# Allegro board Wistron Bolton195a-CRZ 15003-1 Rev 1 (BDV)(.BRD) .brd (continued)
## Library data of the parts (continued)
C57 C59 C71 C81 C89 C102-C105 C108 C111 C117-C123 C134 C142 = C402H22: tolerance: 78.18134.1FL
C82 = C603H36: tolerance: 78.47510.5BL
C88 C106 C270 C288 C302 C306 C326 C445 C6511 C6522 PC4914 = C603H36: tolerance: 78.47520.5BL
C135 = C402H22: tolerance: 78.22420.5FL
C136 C147 PC4906 PC4911 PC4915 PC5103 = C402H22: tolerance: 78.10520.5FL
C175 C186 C188 C194 C254 C255 C484 = C603H36: tolerance: 78.22523.5BL
C177 C328 = C603H36: tolerance: 78.47422.5BL
C178 C324 C421 C435 C477 C486 C488 PC4917 = C603H36: tolerance: 78.10522.5BL
C179 C180 C352 PC4 PC4407 = C402H22: tolerance: 78.10422.5FL
C181 = C805H54: tolerance: 78.47522.51L
C182 C310 C313 C322 C509 C510 C512 PC4414 PC4432 PC4901 PC4908 = C402H22: tolerance: 78.10324.2FL
C184 C230 C235 C236 C266 = C1206H71: tolerance: 78.10525.22L
C185 C190 C192 C195 C197 C200 C205 C413 C420 C436 C450 PC5009 PC5015 = C805H54: tolerance: 78.10623.51L
C211 C223 PC4426-PC4428 PC4445 PC4803 PC4902 PC4903 PC4907 PC4922 PC4923 PC5006 PC5007 = C1206H71: tolerance: 78.10622.52L
C246 = C603H36: tolerance: 78.33135.1BL
C267 = C402H22: tolerance: 78.22224.2FL
C281 C323 PC4405 = C402H22: tolerance: 78.10234.1FL
C292 = C1206H71: tolerance: 78.1022S.22L
C307 C312 C375 C431 C3619 PC2 PC7 PC4415 PC4425 PC4431 PC4804 PC4805 PC4905 PC4909 PC5005 PC5008 PC5208 = C603H36: tolerance: 78.10424.2BL
C327 = C402H22: tolerance: 78.47491.4FL
C353 C354 C356-C365 C368-C371 C373 C374 C376 C377 EC302 EC326-EC330 EC708 EC709 = C402H22: tolerance: 78.5R074.1FL
C379 C388 C392-C397 = C402H22: tolerance: 78.1R574.1FL
C384 = C402H22: tolerance: 78.47134.1FL
C409-C411 C414 C422-C425 = C402H22: tolerance: 78.10324.2FL; signal model: C402H22_SCD01U50V2KX-1GP
C426 = C805H54: tolerance: 78.10620.51L
C428-C430 = C402H22: tolerance: 78.4R774.1FL
C446 = C805H54: tolerance: 78.10693.41L
C452 C460 C680 = C402H22: tolerance: 78.10034.1FL
C495 C496 = C402H22: tolerance: 78.10413.5FL; signal model: C402H22_SCD1U10V2MX-3GP
C506 C3608 C3609 C3614 C3615 C6510 C6514-C6519 C6524 C6526 C6530 C6531 PC4808 PC5012 PC5105 PC5106 PC5205-PC5207 PC5210-PC5226 PC5229 = C603H40: tolerance: 78.22610.5BL
C511 = C402-TO0D2H26: tolerance: 78.47510.5FL
C3603 C3604 C6528 C6529 = C402H22: tolerance: 78.10224.L1L
C4801 PC5110 PC5203 = C402H22: tolerance: 78.10423.2FLDL
C5001 C5002 = C603H36: tolerance: 78.10521.5BLDL
C6101 C6103 C6104 = C402H22: tolerance: 78.10422.2FL
CAM1 = 4260-F08N-00R: tolerance: 20.F2191.008
CMOS1 = SKRBAAE010: tolerance: 62.40089.071
CNVBD2 = 50228-01271-001: tolerance: 20.F1637.012
CPU1 = BGA769M24D5H76: tolerance: 71.KABIN.00U
CRS1 = PSDAT0-09GLBS1ZZ4H1-1: tolerance: 62.10051.661
D1-D3 = SOT23-2D4-312H48: tolerance: 75.00054.R7D
D4 = SOT23-2D4-312H48: tolerance: 75.00054.E7D
D5 = D4724AKH44: tolerance: 83.3R010.C8M
D7 = SOD-523-4H28: tolerance: 75.YSE05.077
D9 D12 D21 = SOT23-2D4-312H46: tolerance: 75.05125.07D
D14 = SOD323AKH40: tolerance: 83.00355.F1F
D19 = SLP2510P8-1H22: tolerance: 83.03010.0A0
D20 D24 = SOT-6H58: tolerance: 075.00005.0B7C
D29 = D5436AKH97: tolerance: 83.P6SBM.AAG
DBGH1 = A2006WV0-2DX7PSA-6T-P: tolerance: 021.D0050.0207
DCIN1 = 2DC-G726-Q15: tolerance: 22.10037.K01
DIMM1 = 1932207-1-U2: tolerance: 62.10017.N91
EC1-EC8 = C402H22: tolerance: 78.6R074.1FL
EC701 EC704 = C402H22: tolerance: 78.10034.L0L
F1 = POLYSW-4633-1H63: tolerance: 69.50013.001
F3 F6 F8 F9 = POLYSW-2114H30: tolerance: 69.48001.081
F4 F7 = POLYSW-3217-UH63: tolerance: 69.42001.291
FANC1 = 87212-0312L: tolerance: 20.F1493.003
FC1 FC4 = C402H22: tolerance: 78.33034.1FL
FC2 = C402H20: tolerance: 78.56034.1FL
G1 G2 PG4401-PG4404 = CON2C-U: tolerance: ZZ.CON2C.XXX
G3 = CON2O-U: tolerance: ZZ.CON2O.XXX
GDT1 = TVS5436-1121H105: tolerance: 069.A0007.0001
H1-H5 = GENS315R158-8-F-A: tolerance: ZZ.SCREW.541
HDD1 = C166KK-12209-L: tolerance: 022.10019.0021
HDMI1 = SKT-HDMI23-150122-9: tolerance: 62.10078.641
HDT1 = DM-ASP-137098-05-01: tolerance: ZZ.F1722.02001
HS1 HS2 = STF237R128H34: tolerance: 34.4YP25.001
HS3 = STF256R109H124: tolerance: 334.0350J.0001
HS4 HS5 = STFT256B126R113H62: tolerance: 334.01Z0E.0001
L1 = L805H42: tolerance: 68.00216.291
L3 L5 L50 L54-L56 L74 L75 = L603H38: tolerance: 68.00335.091
L4 L19 L20 = L1608-UH38: tolerance: 68.00217.351
L7 L9 L11 L13 = L1608-UH38: tolerance: 68.00206.261
L18 PR5201 PR5204 R110-R113 R121 R589 R6103 R6556 R6572 = 0R0603-PAD-1-U: tolerance: ZZ.00PAD.M21
L21 = L3330-1230H95: tolerance: 68.4R710.20S
L22-L25 L41 L44 L47 L72 = L125100-4P-4H24: tolerance: 68.00396.001; signal model: L125100-4P-4H24_COIL-90OHM-100MHZ-5-GP
L27 = L120120-5022-2H237: tolerance: 68.2201C.10Q
L38 = L603H38: tolerance: 68.00335.181
L40 = L125100-4P-4H24: tolerance: 68.00396.001
L49 = L125100-4P-4H24: tolerance: 68.00396.001; signal model: Graser_L49
L51 L53 = L603H38: tolerance: 68.00335.101
L52 = L3030-3009H40: tolerance: 68.4R710.20T
L2901 = L125100-4P-1H37: tolerance: 68.01012.201
LAN1 = QFN32J4-G2D85H36: tolerance: 71.08111.U03
LVDS19 = 196108-30041-U: tolerance: 20.K0386.030
NGFFE1 = AS0BC21-S40BE-7H: tolerance: 062.10003.0611
ODD1 = WATA-07APLDJ6U: tolerance: 020.80475.0007
ODDPW1 = CI0102M1HR0-LF: tolerance: 020.D0007.0102
PC3 PC8 = C805H58: tolerance: 78.10594.41L
PC4402 = C402H22: tolerance: 78.33134.1FLDL
PC4403 PC4442 = C402H22: tolerance: 78.68124.2FL
PC4404 PC4435 = C402H22: tolerance: 78.47034.1FL
PC4406 = C402H22: tolerance: 78.10321.2FLLL
PC4408 PC4409 PC4443 = C805H56: tolerance: 78.10622.51L
PC4410 = C402H22: tolerance: 78.56321.2FL
PC4411 = C402H22: tolerance: 78.10423.5FLLL
PC4413 = C402H22: tolerance: 78.33134.1FL
PC4416 = C402H22: tolerance: 78.47124.2FL
PC4430 = C402H22: tolerance: 078.22423.05FD
PC4437 PC4438 = C402H22: tolerance: 78.47124.2FLLL
PC4439 = C402H22: tolerance: 78.22423.5FL
PC4440 = C402H22: tolerance: 78.10423.5FLDL
PC4441 = C402H22: tolerance: 78.33124.2FL
PC4801 PC5002 PC5104 = C402H22: tolerance: 78.10224.2FLDL
PC4810 PC4919 PC4920 PC5013 = C402H22: tolerance: 78.18034.1FLDL
PC4916 PC4918 = C402H22: tolerance: 78.22034.1FLDL
PC5014 = C805H50: tolerance: 78.10623.51LDL
PC5016 = C603: tolerance: 78.33322.2BL
PC5107 = C603H40: tolerance: 78.22610.5BLDL
PC5109 = C402H22: tolerance: 78.68124.2FLDL
PG4801 PG4802 PG4901-PG4905 = GAP-CLOSE-PWR-3: tolerance: ZZ.CLOSE.001
PL4901 PL4902 = L686647-127318H119: tolerance: 68.3R31A.10V
PL4904 = L115100-2H158: tolerance: 68.R3610.10M
PL4905 = L686647-127318H119: tolerance: 68.R3310.10D
PL4906 PL5001 PL5101 = L686647-127318H119: tolerance: 68.1R51A.10F
PQ4401 PQ4403 = PPAK-8P-5262H40: tolerance: 84.06520.037
PQ4402 PQ4404 PQ4405 = PPAK-8P-5262H40: tolerance: 084.06510.0037
PQ4801 PQ4901 PQ4902 PQ5001 = PPAK-8P-3232H36: tolerance: 84.07410.A37
PQ4802 PQ4903 PQ4904 PQ5002 = PPAK-8P-3232H36: tolerance: 84.07506.037
PR1 = R2512H32: tolerance: 64.R0105.97L
PR2 PR7 R355 R356 = R402H16: tolerance: 64.30035.6DL
PR3 PR4 = R402H16: tolerance: 64.30025.6DL
PR10 PR11 PR13 PR4918 R288 R810 = R402H16: tolerance: 64.15025.6DL
PR12 PR16 PR5206 R296 R338 = R402H16: tolerance: 64.10035.6DL
PR14 PR15 R367 R537 R583 R6577 = R402H16: tolerance: 63.20334.1DL
PR17 = R402H16: tolerance: 64.20035.6DL
PR18 PR4901 R12 R86 R87 R318 R378 R382 R438 R490 R530 R559 R586 = R402H16: tolerance: 63.10434.1DL
PR161 PR4463 PR4464 PR4801 PR4929 R65 R69 R70 R73 R74 R76-R81 R83 R85 R92-R95 R122 R125-R129 R177 R285 R287 R299 R302 R303 R309 R386 R395 R396 R401 R441 R466 R474-R477 R492 R493 R497 R498 R501 R504 R505 R509-R513 R516-R518 R520 R523 R524 R533 R535 R542 R556 R561-R563 R568 R572 R616 R620 R624 R671 R698 R822-R824 R1019 R1020 R6533-R6535 R6543 R6545 R6546 R6548 R6557-R6561 R6563 R6564 R6566 R6578 = R402H16: tolerance: 63.10334.1DL
PR4202 PR4443 PR4921 PR4923 PR4925 PR5006 PR5208 PR5209 R341 R353 R354 R500 R503 R507 R514 R521 R531 R832 R1028-R1030 R6105 R6532 = R402H16: tolerance: 64.10025.6DL
PR4401 PR4435 = R402H16: tolerance: 64.27425.6DL
PR4402 PR4409 PR4424 PR4441 PR4458 PR4462 PR4814 PR5210 R339 = R402H14: tolerance: 64.10R05.6DL
PR4403 PR4428-PR4431 PR4437 PR4440 PR4444 PR4452 PR4454 PR4928 PR5018 R6 R34-R38 R53-R56 R67 R104-R106 R136 R145 R146 R152 R164-R168 R259 R261 R264 R307 R314 R440 R480 R481 R483 R486-R489 R522 R526 R534 R536 R538 R540 R541 R545 R547 R574 R575 R577 R580 R585 R602 R603 R867 R1012 R1014 R4801 R5201 R6104 R6541 = 0R0402-PAD-1: tolerance: ZZ.00PAD.M11
PR4404 = R402H16: tolerance: 64.20515.6DL
PR4405 PR4406 PR4432 PR4433 PR4802 PR4808 PR4810 PR4811 PR4902-PR4904 PR4906 PR4907 PR4910 PR4913-PR4916 PR4930 PR5002 PR5011 PR5013 PR5015-PR5017 PR5021 PR5213 = 0R0805-PAD: tolerance: ZZ.R0805.ZZZ
PR4407 PR4446 PR4450 R18 R387-R394 = R402H16: tolerance: 64.49905.6DL
PR4408 = R402H16: tolerance: 64.56215.6DLDL
PR4410 PR4453 = R402H16: tolerance: 64.26115.6DL
PR4411 = R402H16: tolerance: 64.26735.6DL
PR4412 = R402H16: tolerance: 64.16015.6DL
PR4413 = R402H16: tolerance: 64.82505.6DL
PR4414 PR4451 = R402H16: tolerance: 64.11025.6DL
PR4415 PR4417 PR4420 PR4442 PR4445 PR4455 PR4804 PR4806 PR4812 PR4905 PR4908 PR4909 PR4911 PR4912 PR4919 PR4920 PR5007 PR5009 PR5019 PR5104 = R805H24: tolerance: 63.2R231.16L
PR4416 PR4448 = NTC-402H24-U: tolerance: 69.60013.131
PR4418 = R402H16: tolerance: 64.12015.6DL
PR4421 PR4438 = R402H16: tolerance: 64.38315.6DL
PR4422 PR4439 = NTC-402H22-U: tolerance: 69.60037.021
PR4423 PR4461 = R402H16: tolerance: 64.36515.6DL
PR4425 PR4434 PR4926 = R402H16: tolerance: 64.13335.6DL
PR4426 PR4427 R350 = R805H24: tolerance: 63.1R031.16L
PR4447 R1022-R1027 = R402H14: tolerance: 63.10034.1DL
PR4449 PR4460 R1 R3 R20 R24 R60 R61 R71 R75 R130 R179 R270 R432 R478 R479 R576 R593-R596 R808 R866 R1013 R1015 R4802-R4804 R5002 R5101 R5202 R6110 R6513 R6515 R6531 R6540 R6562 R6565 R6568 R6569 = R402H16: tolerance: 63.R0034.1DL
PR4456 = R402H16: tolerance: 64.34025.6DL
PR4457 = R402H16: tolerance: 64.21515.6DL
PR4459 R5 R7 R9 R16 R17 R97-R100 R139-R142 R345 = R402H16: tolerance: 64.10015.6DL
PR4805 = R402H16: tolerance: 64.78725.6DL
PR4809 = R402H16: tolerance: 64.47035.6DL
PR4813 R96 = R402H16: tolerance: 64.11825.6DL
PR4815 R313 = R402H16: tolerance: 64.33025.6DL
PR4917 = R402H16: tolerance: 64.66515.6DL
PR4922 = R402H16: tolerance: 64.21525.6DL
PR4924 = R402H16: tolerance: 64.68025.6DL
PR4927 = R402H16: tolerance: 64.88725.6DL
PR5001 PR5103 = R402H16: tolerance: 64.5R105.6DL
PR5004 = R402H16: tolerance: 64.51015.6DL
PR5005 = 0R0603-PAD: tolerance: ZZ.R0603.ZZZ
PR5008 = R402H16: tolerance: 64.62035.6DL
PR5020 R172 = R402H16: tolerance: 64.39225.6DL
PR5022 = R402H16: tolerance: 64.R0005.6DL
PR5101 PR5102 PR5211 PR5212 R109 R115-R117 R119 R278 R346 R429 R1021 R6536-R6539 = 0R0805-PAD-1-U: tolerance: ZZ.00PAD.M31
PR5105 = R402H16: tolerance: 64.10235.6DL
PR5107 = R402H16: tolerance: 64.51025.6DL
PR5108 = R402H16: tolerance: 64.18025.6DL
PT4402 PT4403 PT4406 PT4407 PT4411 = SE361416H237: tolerance: 79.5671V.30L
PT4404 PT5001 = CT7343H83: tolerance: 79.3371V.2PL
PT4902 PT4903 = SE331721H237: tolerance: 79.22710.E0L
PU1 = SOT23-2D8-312H58: tolerance: 74.02138.03B
PU2 = SOIC8H69: tolerance: 84.04407.G37
PU4401 = QFN40-G3D5H32: tolerance: 74.62771.033
PU4801 = DFN10G3-G265175H32: tolerance: 74.08237.B73
PU4901 = QFN20-G1D75H32: tolerance: 74.08243.073
PU5001 = QFN20-G1D75H32: tolerance: 74.08207.C73
PU5101 = DFN10G3-G265175H32: tolerance: 74.08068.A43
PU5201 = SOT-23-5H52: tolerance: 74.01339.B3F
PWRBT1 = 88511-0641: tolerance: 20.K0473.006
Q1 Q39 Q4803 = SOT23DGS2D4H44: tolerance: 84.27002.W31
Q2 = SOT23CBE2D4H44: tolerance: 84.T3904.H11
Q4 Q27 Q29 Q34 Q42 Q45 Q49 Q76 = SOT-363H44: tolerance: 84.2N702.A3F
Q26 Q35 Q36 Q38 Q98 Q99 Q4808 = SOT23DGS2D4H44: tolerance: 84.2N702.J31
Q28 Q32 Q41 Q52 = SOT-23-10H44: tolerance: 84.03906.F11
Q33 Q75 Q82 Q83 Q100 Q101 Q4401 Q4807 = SOT23DGS2D4H48: tolerance: 84.2N702.E31
Q37 Q4402 = SOT23CBE2D4H44: tolerance: 84.T3904.C11
Q40 U16 U17 = SOT23DGS2D8H50: tolerance: 84.03418.A31
Q43 = SOT23DGS2D8H50: tolerance: 84.03413.B31
Q44 = SOT-23-10H44: tolerance: 84.03904.L06
Q48 Q50 Q51 Q57 Q4802 Q4804-Q4806 = SOT23DGS2D4H44: tolerance: 84.27002.Z31
Q78 = SOIC8H75: tolerance: 084.PA010.0037
Q4801 = SOT23DGS2D4H35: tolerance: 84.3K329.031
R2 R21 R23 R25-R27 R30-R33 R39-R44 R46-R48 R88-R90 R124 R175 R176 R234 R286 R306 R317 R364 R365 R379 R402 R437 R491 R546 R548-R553 R557 R560 R579 R581 R582 R584 R830 R982 R6547 R6549 R6552-R6555 R6570 R6571 R6573 R6574 R6576 = R402H16: tolerance: 63.10234.1DL
R4 = R402H16: tolerance: 64.39R25.6DL
R8 = R402H16: tolerance: 64.16915.6DL
R10 R13-R15 R807 R826-R828 = R402H16: tolerance: 64.15005.6DL
R11 = R402H16: tolerance: 64.20015.6DL
R19 R22 R49-R51 R266 R464 R813 = R402H16: tolerance: 63.30134.1DL
R28 R29 R377 = R402H16: tolerance: 64.51105.6DL
R45 R310 R319 R359 R360 R381 R383 R439 R527 R591 R592 R597-R601 R604-R609 R617 R622 R812 R4401-R4403 R6516 R6550 R6551 = R402H16: tolerance: 63.47234.1DL
R52 R131 R134 R135 R232 R515 R619 R6512 = R402H16: tolerance: 63.22234.1DL
R57 R58 = R402H16: tolerance: 63.18234.1DL
R59 = R402H16: tolerance: 63.22134.1DL
R62 R316 R376 R434 R435 R555 R578 = R402H16: tolerance: 63.47334.1DL
R63 R64 R174 R430 R431 R433 R539 R543 = R402H16: tolerance: 63.33034.1DL
R84 = R603H22: tolerance: 63.20634.15L
R101-R103 = R402H16: tolerance: 63.22034.1DL
R108 = R603H22: tolerance: 64.10045.55L
R123 R6544 = R402H16: tolerance: 63.20134.1DL
R132 R133 R6575 = R402H16: tolerance: 63.20234.1DL
R169 R809 = R402H16: tolerance: 64.20025.6DL
R235 R236 R6511 = R402H16: tolerance: 63.22334.1DL
R238 R240 R623 = R402H16: tolerance: 63.75034.1DL
R268 = R402H16: tolerance: 64.24915.6DL
R269 R802-R804 = R805H24: tolerance: 63.R0031.16L
R271 R272 = 0R0402-PAD-1: tolerance: ZZ.00PAD.M11; signal model: 0R0402-PAD-1_0R0402-PAD-2-GP
R284 = R603H22: tolerance: 63.75033.15L
R315 R380 R436 = R402H16: tolerance: 63.33434.1DL
R322 R544 = R402H14: tolerance: 64.10005.6DL
R342 = 0R1206-PAD-1: tolerance: ZZ.R1206.ZZ1
R347 = R805H24: tolerance: 63.20131.16L
R348 R349 = R1206H26: tolerance: 64.R3305.41L
R374 R375 = R402H14: tolerance: 63.10134.1DL
R384 = R402H16: tolerance: 63.10534.1DL
R463 R588 R590 = R603H22: tolerance: 63.00000.00L
R499 R508 = R402H16: tolerance: 64.17825.6DL
R502 = R402H16: tolerance: 64.64915.6DL
R519 = R402H16: tolerance: 64.95325.6DL
R529 = R402H16: tolerance: 64.47015.6DL
R587 = R402H16: tolerance: 64.12025.6DL
R610 R611 R613-R615 = R402H16: tolerance: 63.10434.L0L
R618 = R805H24: tolerance: 63.30131.16L
R621 = R805H24: tolerance: 63.15131.16L
R1031 = R603H22: tolerance: 63.33133.15L
R6517 = R402H16: tolerance: 64.82015.6DL
R6579 = R402H16: tolerance: 64.56015.6DL
RJ1 = C100LS-10809-L: tolerance: 022.10001.0041
RN1 = SMD-ARES4-2H18-U: tolerance: 66.1033A.04L
RN2 = ARES8-CN24-UH20: tolerance: 66.33036.A8L
RN3 RN5 RN12 RN15-RN17 = ARES2H16: tolerance: 66.22236.04L
RN4 RN6 RN7 RN9 RN11 RN22 = ARES8-CN24-MUH20: tolerance: 66.10336.08L
RN8 = SMD-ARES4H18: tolerance: 66.33036.04L
RN10 RN18-RN21 = ARES2H18: tolerance: 66.10336.04L
RT1 RT2 = NTC-402H22-U: tolerance: 69.60011.121
SPI1 = G6179-1000000-U: tolerance: 62.10076.011
SPK1 = 87212-04G2: tolerance: 20.F1889.004
TOUCH1 = 50228-0057C-001: tolerance: 20.F2220.005
TP1-TP18 TP23 TP24 TP27 TP29 TP30 TP33-TP35 TP64-TP70 = TPAD24: tolerance: ZZ.PAD24.001
TP19-TP22 TP25 TP28 TP31 TP32 TP55 = TPAD28-1-U: tolerance: ZZ.00PAD.1F1
TR3 = L125100-4P-1H28: tolerance: 68.10129.201; signal model: Graser_TR3
TR4 = L125100-4P-1H28: tolerance: 68.10129.201; signal model: Graser_TR4
TR5 = L125100-4P-1H28: tolerance: 68.10129.201; signal model: Graser_TR5
TR6 = L125100-4P-1H28: tolerance: 68.10129.201; signal model: Graser_TR6
TR11 TR12 TR25 TR26 = L125100-4P-1H24: tolerance: 68.11500.201; signal model: L125100-4P-1H24_COIL-50OHM-GP
TR27 TR28 = L125100-4P-1H24: tolerance: 68.11500.201
U9 U10 = SOT-6H58: tolerance: 75.09904.07C
U12 U13 = SON14J3020-G2610H32: tolerance: 74.03523.A73
U18 U20 U22 = SOT-6-1H50: tolerance: 84.06402.B3D
U23-U25 = DFN10G2510H26: tolerance: 75.01045.073
U30 = SOIC8-1H86: tolerance: 72.25640.D01
U31 = PQFP128H134: tolerance: 71.08732.00E
U38 = QFN48J6-G4D55H40: tolerance: 71.02136.B03
U39 = SOT-23-1H44: tolerance: 75.00099.07D
U48 = SOIC8H69: tolerance: 74.00358.K11
U51 = SOT-23-5H58: tolerance: 074.00524.0B9F
U56 = SOIC8H69: tolerance: 072.25010.0A01
U58 = SOIC8H69: tolerance: 72.24C64.E01
U59 = QFN20-G2D1H34: tolerance: 74.00554.073
U6502 = SOIC8H69: tolerance: 74.05606.A71
U6503 = LQFP64H63: tolerance: 71.08772.B0G
USB2S1 USB2S2 = SKT-USB6-145137-6: tolerance: 22.10218.H01
USB3S1 = SKT-USB11-139165-9: tolerance: 22.10341.B51
X1 = SMD49-6914-0403H56: tolerance: 82.30001.661
X2 = OSC-3225-4P-3H36: tolerance: 82.30026.271
X3 = OSC-3225-4P-4H36: tolerance: 82.30020.G71
XF1 = XFORM24Z151100H160: tolerance: 68.89240.30B; signal model: XFORM24Z151100H160_XFORM-24P-27-GP

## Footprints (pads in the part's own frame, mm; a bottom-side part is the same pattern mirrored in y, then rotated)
0R0402-PAD-1
  custom 0.14x0.14 smd: 1(0,0.445) 2(0,-0.445)
0R0603-PAD
  custom 0.216x0.216 smd: 1(0,0.851) 2(0,-0.673)
0R0603-PAD-1-U
  custom 0.216x0.216 smd: 1(0,0.762) 2(0,-0.762)
0R0805-PAD
  rect 1.397x1.562 smd: 1(0,0.965)
  rect 1.397x1.569 smd: 2(0,-0.965)
0R0805-PAD-1-U
  rect 1.397x1.562 smd: 1(0,0.965)
  rect 1.397x1.569 smd: 2(0,-0.965)
0R1206-PAD-1
  rect 1.651x2.057 smd: 1(0,1.397) 2(0,-1.397)
2DC-G726-Q15
  round 0.254 hole 2.413 unplated: (0,0)
  oval 2.718x1.727 hole 2.007x1.016: 1(0,7.25)
  oval 1.727x2.718 hole 1.016x2.007: 2(-3.1,6.3) 3(-5.2,6.3) 4(3.4,6.3)
  oval 1.727x3.023 hole 1.016x2.311: 5(3.75,-1) 6(-6.15,-1)
4260-F08N-00R
  rect 0.508x0.991 smd: 1(2.8,1.945) 2(2,1.945) 3(1.2,1.945) 4(0.4,1.945) 5(-0.4,1.945) 6(-1.2,1.945) 7(-2,1.945) 8(-2.8,1.945)
  rect 1.194x1.702 smd: 9(4.097,0) 10(-4.097,0)
50228-0057C-001
  rect 0.61x1.549 smd: 1(2,-2.525) 2(1,-2.525) 3(0,-2.525) 4(-1,-2.525) 5(-2,-2.525)
  rect 1.194x1.803 smd: 6(3.3,0) 7(-3.3,0)
50228-01271-001
  rect 0.61x1.549 smd: 1(5.5,-2.525) 2(4.5,-2.525) 3(3.5,-2.525) 4(2.5,-2.525) 5(1.5,-2.525) 6(0.5,-2.525) 7(-0.5,-2.525) 8(-1.5,-2.525) 9(-2.5,-2.525) 10(-3.5,-2.525) 11(-4.5,-2.525) 12(-5.5,-2.525)
  rect 1.194x1.803 smd: 13(6.8,0) 14(-6.8,0)
87212-04G2
  rect 0.406x1.651 smd: 1(-1.5,-2.577) 2(-0.5,-2.577) 3(0.5,-2.577) 4(1.5,-2.577)
  rect 1.194x1.803 smd: 5(-2.797,0) 6(2.797,0)
87212-0312L
  rect 0.61x1.549 smd: 1(-1,-2.525) 2(0,-2.525) 3(1,-2.525)
  rect 1.194x1.803 smd: 4(-2.3,0) 5(2.3,0)
88511-0641
  rect 0.305x1.295 smd: 1(-1.25,2.798) 2(-0.75,2.798) 3(-0.25,2.798) 4(0.25,2.798) 5(0.75,2.798) 6(1.25,2.798)
  rect 1.803x1.397 smd: 7(-2.902,0) 8(2.902,0)
196108-30041-U
  rect 0.508x1.295 smd: 1(-14.5,2.65) 2(-13.5,2.65) 3(-12.5,2.65) 4(-11.5,2.65) 5(-10.5,2.65) 6(-9.5,2.65) 7(-8.5,2.65) 8(-7.5,2.65) 9(-6.5,2.65) 10(-5.5,2.65) 11(-4.5,2.65) 12(-3.5,2.65) 13(-2.5,2.65) 14(-1.5,2.65) 15(-0.5,2.65) 16(0.5,2.65) 17(1.5,2.65) 18(2.5,2.65) 19(3.5,2.65) 20(4.5,2.65) 21(5.5,2.65) 22(6.5,2.65) 23(7.5,2.65) 24(8.5,2.65) 25(9.5,2.65) 26(10.5,2.65) 27(11.5,2.65) 28(12.5,2.65) 29(13.5,2.65) 30(14.5,2.65)
  rect 1.803x1.397 smd: 31(-16.65,0) 32(16.65,0)
1932207-1-U2
  round 0.254 hole 1.651 unplated: (-33.4,0)
  round 0.254 hole 1.118 unplated: (33.4,0)
  custom 0.114x0.114 smd: 1(-31.65,-4.1) 2(-31.35,4.1) 3(-31.05,-4.1) 4(-30.75,4.1) 5(-30.45,-4.1) 6(-30.15,4.1) 7(-29.85,-4.1) 8(-29.55,4.1) 9(-29.25,-4.1) 10(-28.95,4.1) 11(-28.65,-4.1) 12(-28.35,4.1) 13(-28.05,-4.1) 14(-27.75,4.1) 15(-27.45,-4.1) 16(-27.15,4.1) 17(-26.85,-4.1) 18(-26.55,4.1) 19(-26.25,-4.1) 20(-25.95,4.1) 21(-25.65,-4.1) 22(-25.35,4.1) 23(-25.05,-4.1) 24(-24.75,4.1) 25(-24.45,-4.1) 26(-24.15,4.1) 27(-23.85,-4.1) 28(-23.55,4.1) 29(-23.25,-4.1) 30(-22.95,4.1) 31(-22.65,-4.1) 32(-22.35,4.1) 33(-22.05,-4.1) 34(-21.75,4.1) 35(-21.45,-4.1) 36(-21.15,4.1) 37(-20.85,-4.1) 38(-20.55,4.1) 39(-20.25,-4.1) 40(-19.95,4.1) 41(-19.65,-4.1) 42(-19.35,4.1) 43(-19.05,-4.1) 44(-18.75,4.1) 45(-18.45,-4.1) 46(-18.15,4.1) 47(-17.85,-4.1) 48(-17.55,4.1) 49(-17.25,-4.1) 50(-16.95,4.1) 51(-16.65,-4.1) 52(-16.35,4.1) 53(-16.05,-4.1) 54(-15.75,4.1) 55(-15.45,-4.1) 56(-15.15,4.1) 57(-14.85,-4.1) 58(-14.55,4.1) 59(-14.25,-4.1) 60(-13.95,4.1) 61(-13.65,-4.1) 62(-13.35,4.1) 63(-13.05,-4.1) 64(-12.75,4.1) 65(-12.45,-4.1) 66(-12.15,4.1) 67(-11.85,-4.1) 68(-11.55,4.1) 69(-11.25,-4.1) 70(-10.95,4.1) 71(-10.65,-4.1) 72(-10.35,4.1) 73(-7.65,-4.1) 74(-7.35,4.1) 75(-7.05,-4.1) 76(-6.75,4.1) 77(-6.45,-4.1) 78(-6.15,4.1) 79(-5.85,-4.1) 80(-5.55,4.1) 81(-5.25,-4.1) 82(-4.95,4.1) 83(-4.65,-4.1) 84(-4.35,4.1) 85(-4.05,-4.1) 86(-3.75,4.1) 87(-3.45,-4.1) 88(-3.15,4.1) 89(-2.85,-4.1) 90(-2.55,4.1) 91(-2.25,-4.1) 92(-1.95,4.1) 93(-1.65,-4.1) 94(-1.35,4.1) 95(-1.05,-4.1) 96(-0.75,4.1) 97(-0.45,-4.1) 98(-0.15,4.1) 99(0.15,-4.1) 100(0.45,4.1) 101(0.75,-4.1) 102(1.05,4.1) 103(1.35,-4.1) 104(1.65,4.1) 105(1.95,-4.1) 106(2.25,4.1) 107(2.55,-4.1) 108(2.85,4.1) 109(3.15,-4.1) 110(3.45,4.1) 111(3.75,-4.1) 112(4.05,4.1) 113(4.35,-4.1) 114(4.65,4.1) 115(4.95,-4.1) 116(5.25,4.1) 117(5.55,-4.1) 118(5.85,4.1) 119(6.15,-4.1) 120(6.45,4.1) 121(6.75,-4.1) 122(7.05,4.1) 123(7.35,-4.1) 124(7.65,4.1) 125(7.95,-4.1) 126(8.25,4.1) 127(8.55,-4.1) 128(8.85,4.1) 129(9.15,-4.1) 130(9.45,4.1) 131(9.75,-4.1) 132(10.05,4.1) 133(10.35,-4.1) 134(10.65,4.1) 135(10.95,-4.1) 136(11.25,4.1) 137(11.55,-4.1) 138(11.85,4.1) 139(12.15,-4.1) 140(12.45,4.1) 141(12.75,-4.1) 142(13.05,4.1) 143(13.35,-4.1) 144(13.65,4.1) 145(13.95,-4.1) 146(14.25,4.1) 147(14.55,-4.1) 148(14.85,4.1) 149(15.15,-4.1) 150(15.45,4.1) 151(15.75,-4.1) 152(16.05,4.1) 153(16.35,-4.1) 154(16.65,4.1) 155(16.95,-4.1) 156(17.25,4.1) 157(17.55,-4.1) 158(17.85,4.1) 159(18.15,-4.1) 160(18.45,4.1) 161(18.75,-4.1) 162(19.05,4.1) 163(19.35,-4.1) 164(19.65,4.1) 165(19.95,-4.1) 166(20.25,4.1) 167(20.55,-4.1) 168(20.85,4.1) 169(21.15,-4.1) 170(21.45,4.1) 171(21.75,-4.1) 172(22.05,4.1) 173(22.35,-4.1) 174(22.65,4.1) 175(22.95,-4.1) 176(23.25,4.1) 177(23.55,-4.1) 178(23.85,4.1) 179(24.15,-4.1) 180(24.45,4.1) 181(24.75,-4.1) 182(25.05,4.1) 183(25.35,-4.1) 184(25.65,4.1) 185(25.95,-4.1) 186(26.25,4.1) 187(26.55,-4.1) 188(26.85,4.1) 189(27.15,-4.1) 190(27.45,4.1) 191(27.75,-4.1) 192(28.05,4.1) 193(28.35,-4.1) 194(28.65,4.1) 195(28.95,-4.1) 196(29.25,4.1) 197(29.55,-4.1) 198(29.85,4.1) 199(30.15,-4.1) 200(30.45,4.1) 201(30.75,-4.1) 202(31.05,4.1) 203(31.35,-4.1) 204(31.65,4.1)
  rect 3.505x4.597 smd: 205(-32.8,12) 206(32.8,12)
A2006WV0-2DX7PSA-6T-P
  rect 0.813x2.692 smd: 1(-6,2.1) 2(-6,-2.1) 3(-4,2.1) 4(-4,-2.1) 5(-2,2.1) 7(0,2.1) 8(0,-2.1) 9(2,2.1) 10(2,-2.1) 11(4,2.1) 12(4,-2.1) 13(6,2.1) 14(6,-2.1)
  rect 0.025x0.025 smd: 6(-2,-2.1)
AAA-BAT-034-K01
  round 0.254 hole 1.067 unplated: (-7.5,0)
  round 0.254 hole 1.372 unplated: (0,0)
  rect 2.794x3.607 smd: 1(6.2,0)
  rect 2.997x2.591 smd: 2(-15.1,0)
ARES2H16
  rect 0.356x0.66 smd: 1(-0.325,-0.599) 2(0.325,-0.599) 3(0.325,0.599) 4(-0.325,0.599)
ARES2H18
  rect 0.356x0.66 smd: 1(-0.325,-0.599) 2(0.325,-0.599) 3(0.325,0.599) 4(-0.325,0.599)
ARES8-CN24-MUH20
  rect 0.61x0.66 smd: 1(-0.9,-0.486) 4(0.9,-0.486) 5(0.9,0.486) 8(-0.9,0.486)
  rect 0.305x0.66 smd: 2(-0.25,-0.486) 3(0.25,-0.486) 6(0.25,0.486) 7(-0.25,0.486)
ARES8-CN24-UH20
  rect 0.61x0.66 smd: 1(-0.9,-0.486) 4(0.9,-0.486) 5(0.9,0.486) 8(-0.9,0.486)
  rect 0.305x0.66 smd: 2(-0.25,-0.486) 3(0.25,-0.486) 6(0.25,0.486) 7(-0.25,0.486)
AS0BC21-S40BE-7H
  round 0.254 hole 1.168 unplated: (-10,0)
  round 0.254 hole 1.651 unplated: (10,0)
  rect 0.305x1.549 smd: 1(-9.25,5.275) 2(-9,-2.275) 3(-8.75,5.275) 4(-8.5,-2.275) 5(-8.25,5.275) 6(-8,-2.275) 7(-7.75,5.275) 8(-7.5,-2.275) 9(-7.25,5.275) 10(-7,-2.275) 11(-6.75,5.275) 12(-6.5,-2.275) 13(-6.25,5.275) 14(-6,-2.275) 15(-5.75,5.275) 16(-5.5,-2.275) 17(-5.25,5.275) 18(-5,-2.275) 19(-4.75,5.275) 20(-4.5,-2.275) 21(-4.25,5.275) 22(-4,-2.275) 23(-3.75,5.275) 32(-1.5,-2.275) 33(-1.25,5.275) 34(-1,-2.275) 35(-0.75,5.275) 36(-0.5,-2.275) 37(-0.25,5.275) 38(0,-2.275) 39(0.25,5.275) 40(0.5,-2.275) 41(0.75,5.275) 42(1,-2.275) 43(1.25,5.275) 44(1.5,-2.275) 45(1.75,5.275) 46(2,-2.275) 47(2.25,5.275) 48(2.5,-2.275) 49(2.75,5.275) 50(3,-2.275) 51(3.25,5.275) 52(3.5,-2.275) 53(3.75,5.275) 54(4,-2.275) 55(4.25,5.275) 56(4.5,-2.275) 57(4.75,5.275) 58(5,-2.275) 59(5.25,5.275) 60(5.5,-2.275) 61(5.75,5.275) 62(6,-2.275) 63(6.25,5.275) 64(6.5,-2.275) 65(6.75,5.275) 66(7,-2.275) 67(7.25,5.275) 68(7.5,-2.275) 69(7.75,5.275) 70(8,-2.275) 71(8.25,5.275) 72(8.5,-2.275) 73(8.75,5.275) 74(9,-2.275) 75(9.25,5.275)
  rect 1.194x2.743 smd: 76(-10.35,4.5) 77(10.35,4.5)
BGA769M24D5H76
  round 0.4 smd: A2(-10.7,11.3) A3(-9.95,11.3) A39(9.95,11.3) A40(10.7,11.3) AA4(-9.2,0) AA5(-8.4,0) AA7(-7.6,0) AA8(-6.8,0) AA10(-6,0) AA11(-5,0) AA13(-4,0) AA15(-3,0) AA17(-2,0) AA19(-1,0) AA21(0,0) AA23(1,0) AA25(2,0) AA27(3,0) AA29(4,0) AA31(5,0) AA32(6,0) AA34(6.8,0) AA35(7.6,0) AA37(8.4,0) AA38(9.2,0) AC4(-9.2,-1.1) AC5(-8.4,-1.1) AC7(-7.6,-1.1) AC8(-6.8,-1.1) AC10(-6,-1.1) AC11(-5,-1) AC13(-4,-1) AC15(-3,-1) AC17(-2,-1) AC19(-1,-1) AC21(0,-1) AC23(1,-1) AC25(2,-1) AC27(3,-1) AC29(4,-1) AC31(5,-1) AC32(6,-1.1) AC34(6.8,-1.1) AC35(7.6,-1.1) AC37(8.4,-1.1) AC38(9.2,-1.1) AE4(-9.2,-2.2) AE5(-8.4,-2.2) AE7(-7.6,-2.2) AE8(-6.8,-2.2) AE10(-6,-2.2) AE11(-5,-2) AE13(-4,-2) AE15(-3,-2) AE17(-2,-2) AE19(-1,-2) AE21(0,-2) AE23(1,-2) AE25(2,-2) AE27(3,-2) AE29(4,-2) AE31(5,-2) AE32(6,-2.2) AE34(6.8,-2.2) AE35(7.6,-2.2) AE37(8.4,-2.2) AE38(9.2,-2.2) AG4(-9.2,-3.3) AG5(-8.4,-3.3) AG7(-7.6,-3.3) AG8(-6.8,-3.3) AG10(-6,-3.3) AG11(-5,-3) AG13(-4,-3) AG15(-3,-3) AG17(-2,-3) AG19(-1,-3) AG21(0,-3) AG23(1,-3) AG25(2,-3) AG27(3,-3) AG29(4,-3) AG31(5,-3) AG32(6,-3.3) AG34(6.8,-3.3) AG35(7.6,-3.3) AG37(8.4,-3.3) AG38(9.2,-3.3) AJ4(-9.2,-4.4) AJ5(-8.4,-4.4) AJ7(-7.6,-4.4) AJ8(-6.8,-4.4) AJ10(-6,-4.4) AJ11(-5,-4) AJ13(-4,-4) AJ15(-3,-4) AJ17(-2,-4) AJ19(-1,-4) AJ21(0,-4) AJ23(1,-4) AJ25(2,-4) AJ27(3,-4) AJ29(4,-4) AJ31(5,-4) AJ32(6,-4.4) AJ34(6.8,-4.4) AJ35(7.6,-4.4) AJ37(8.4,-4.4) AJ38(9.2,-4.4) AL4(-9.2,-5.5) AL5(-8.4,-5.5) AL7(-7.6,-5.5) AL8(-6.8,-5.5) AL10(-6,-5.5) AL11(-5,-5) AL13(-4,-5) AL15(-3,-5) AL17(-2,-5) AL19(-1,-5) AL21(0,-5) AL23(1,-5) AL25(2,-5) AL27(3,-5) AL29(4,-5) AL31(5,-5) AL32(6,-5.5) AL34(6.8,-5.5) AL35(7.6,-5.5) AL37(8.4,-5.5) AL38(9.2,-5.5) AM11(-5.5,-6) AM13(-4.4,-6) AM15(-3.3,-6) AM17(-2.2,-6) AM19(-1.1,-6) AM21(0,-6) AM23(1.1,-6) AM25(2.2,-6) AM27(3.3,-6) AM29(4.4,-6) AM31(5.5,-6) AN4(-9.2,-6.6) AN5(-8.4,-6.6) AN7(-7.6,-6.6) AN8(-6.8,-6.6) AN34(6.8,-6.6) AN35(7.6,-6.6) AN37(8.4,-6.6) AN38(9.2,-6.6) AP11(-5.5,-6.8) AP13(-4.4,-6.8) AP15(-3.3,-6.8) AP17(-2.2,-6.8) AP19(-1.1,-6.8) AP21(0,-6.8) AP23(1.1,-6.8) AP25(2.2,-6.8) AP27(3.3,-6.8) AP29(4.4,-6.8) AP31(5.5,-6.8) AR4(-9.2,-7.7) AR5(-8.4,-7.7) AR7(-7.6,-7.7) AR11(-5.5,-7.6) AR13(-4.4,-7.6) AR15(-3.3,-7.6) AR17(-2.2,-7.6) AR19(-1.1,-7.6) AR21(0,-7.6) AR23(1.1,-7.6) AR25(2.2,-7.6) AR27(3.3,-7.6) AR29(4.4,-7.6) AR31(5.5,-7.6) AR35(7.6,-7.7) AR37(8.4,-7.7) AR38(9.2,-7.7) AU4(-9.2,-8.8) AU7(-7.7,-8.4) AU9(-6.6,-8.4) AU11(-5.5,-8.4) AU13(-4.4,-8.4) AU15(-3.3,-8.4) AU17(-2.2,-8.4) AU19(-1.1,-8.4) AU21(0,-8.4) AU23(1.1,-8.4) AU25(2.2,-8.4) AU27(3.3,-8.4) AU29(4.4,-8.4) AU31(5.5,-8.4) AU33(6.6,-8.4) AU35(7.7,-8.4) AU38(9.2,-8.8) AV7(-7.7,-9.2) AV9(-6.6,-9.2) AV11(-5.5,-9.2) AV13(-4.4,-9.2) AV15(-3.3,-9.2) AV17(-2.2,-9.2) AV19(-1.1,-9.2) AV21(0,-9.2) AV23(1.1,-9.2) AV25(2.2,-9.2) AV27(3.3,-9.2) AV29(4.4,-9.2) AV31(5.5,-9.2) AV33(6.6,-9.2) AV35(7.7,-9.2) AW1(-11.3,-9.95) AW41(11.3,-9.95) AY1(-11.3,-10.7) AY2(-10.6,-10.6) AY40(10.6,-10.6) AY41(11.3,-10.7) B1(-11.3,10.7) B2(-10.6,10.6) B40(10.6,10.6) B41(11.3,10.7) BA2(-10.7,-11.3) BA3(-9.95,-11.3) BA39(9.95,-11.3) BA40(10.7,-11.3) C1(-11.3,9.95) C41(11.3,9.95) D7(-7.7,9.2) D9(-6.6,9.2) D11(-5.5,9.2) D13(-4.4,9.2) D15(-3.3,9.2) D17(-2.2,9.2) D19(-1.1,9.2) D21(0,9.2) D23(1.1,9.2) D25(2.2,9.2) D27(3.3,9.2) D29(4.4,9.2) D31(5.5,9.2) D33(6.6,9.2) D35(7.7,9.2) E4(-9.2,8.8) E7(-7.7,8.4) E9(-6.6,8.4) E11(-5.5,8.4) E13(-4.4,8.4) E15(-3.3,8.4) E17(-2.2,8.4) E19(-1.1,8.4) E21(0,8.4) E23(1.1,8.4) E25(2.2,8.4) E27(3.3,8.4) E29(4.4,8.4) E31(5.5,8.4) E33(6.6,8.4) E35(7.7,8.4) E38(9.2,8.8) G4(-9.2,7.7) G5(-8.4,7.7) G7(-7.6,7.7) G11(-5.5,7.6) G13(-4.4,7.6) G15(-3.3,7.6) G17(-2.2,7.6) G19(-1.1,7.6) G21(0,7.6) G23(1.1,7.6) G25(2.2,7.6) G27(3.3,7.6) G29(4.4,7.6) G31(5.5,7.6) G35(7.6,7.7) G37(8.4,7.7) G38(9.2,7.7) H11(-5.5,6.8) H13(-4.4,6.8) H15(-3.3,6.8) H17(-2.2,6.8) H19(-1.1,6.8) H21(0,6.8) H23(1.1,6.8) H25(2.2,6.8) H27(3.3,6.8) H29(4.4,6.8) H31(5.5,6.8) J4(-9.2,6.6) J5(-8.4,6.6) J7(-7.6,6.6) J8(-6.8,6.6) J34(6.8,6.6) J35(7.6,6.6) J37(8.4,6.6) J38(9.2,6.6) K11(-5.5,6) K13(-4.4,6) K15(-3.3,6) K17(-2.2,6) K19(-1.1,6) K21(0,6) K23(1.1,6) K25(2.2,6) K27(3.3,6) K29(4.4,6) K31(5.5,6) L4(-9.2,5.5) L5(-8.4,5.5) L7(-7.6,5.5) L8(-6.8,5.5) L10(-6,5.5) L11(-5,5) L13(-4,5) L15(-3,5) L17(-2,5) L19(-1,5) L21(0,5) L23(1,5) L25(2,5) L27(3,5) L29(4,5) L31(5,5) L32(6,5.5) L34(6.8,5.5) L35(7.6,5.5) L37(8.4,5.5) L38(9.2,5.5) N4(-9.2,4.4) N5(-8.4,4.4) N7(-7.6,4.4) N8(-6.8,4.4) N10(-6,4.4) N11(-5,4) N13(-4,4) N15(-3,4) N17(-2,4) N19(-1,4) N21(0,4) N23(1,4) N25(2,4) N27(3,4) N29(4,4) N31(5,4) N32(6,4.4) N34(6.8,4.4) N35(7.6,4.4) N37(8.4,4.4) N38(9.2,4.4) R4(-9.2,3.3) R5(-8.4,3.3) R7(-7.6,3.3) R8(-6.8,3.3) R10(-6,3.3) R11(-5,3) R13(-4,3) R15(-3,3) R17(-2,3) R19(-1,3) R21(0,3) R23(1,3) R25(2,3) R27(3,3) R29(4,3) R31(5,3) R32(6,3.3) R34(6.8,3.3) R35(7.6,3.3) R37(8.4,3.3) R38(9.2,3.3) U4(-9.2,2.2) U5(-8.4,2.2) U7(-7.6,2.2) U8(-6.8,2.2) U10(-6,2.2) U11(-5,2) U13(-4,2) U15(-3,2) U17(-2,2) U19(-1,2) U21(0,2) U23(1,2) U25(2,2) U27(3,2) U29(4,2) U31(5,2) U32(6,2.2) U34(6.8,2.2) U35(7.6,2.2) U37(8.4,2.2) U38(9.2,2.2) W4(-9.2,1.1) W5(-8.4,1.1) W7(-7.6,1.1) W8(-6.8,1.1) W10(-6,1.1) W11(-5,1) W13(-4,1) W15(-3,1) W17(-2,1) W19(-1,1) W21(0,1) W23(1,1) W25(2,1) W27(3,1) W29(4,1) W31(5,1) W32(6,1.1) W34(6.8,1.1) W35(7.6,1.1) W37(8.4,1.1) W38(9.2,1.1)
  round 0.3 smd: A4(-9.35,10.95) A5(-8.8,11.3) A6(-8.25,10.95) A7(-7.7,11.3) A8(-7.15,10.95) A9(-6.6,11.3) A10(-6.05,10.95) A11(-5.5,11.3) A12(-4.95,10.95) A13(-4.4,11.3) A14(-3.85,10.95) A15(-3.3,11.3) A16(-2.75,10.95) A17(-2.2,11.3) A18(-1.65,10.95) A19(-1.1,11.3) A20(-0.55,10.95) A21(0,11.3) A22(0.55,10.95) A23(1.1,11.3) A24(1.65,10.95) A25(2.2,11.3) A26(2.75,10.95) A27(3.3,11.3) A28(3.85,10.95) A29(4.4,11.3) A30(4.95,10.95) A31(5.5,11.3) A32(6.05,10.95) A33(6.6,11.3) A34(7.15,10.95) A35(7.7,11.3) A36(8.25,10.95) A37(8.8,11.3) A38(9.35,10.95) AA1(-11.3,0) AA2(-10.6,0) AA3(-9.9,0) AA39(9.9,0) AA40(10.6,0) AA41(11.3,0) AB1(-10.95,-0.55) AB2(-10.25,-0.55) AB40(10.25,-0.55) AB41(10.95,-0.55) AC1(-11.3,-1.1) AC2(-10.6,-1.1) AC3(-9.9,-1.1) AC39(9.9,-1.1) AC40(10.6,-1.1) AC41(11.3,-1.1) AD1(-10.95,-1.65) AD2(-10.25,-1.65) AD40(10.25,-1.65) AD41(10.95,-1.65) AE1(-11.3,-2.2) AE2(-10.6,-2.2) AE3(-9.9,-2.2) AE39(9.9,-2.2) AE40(10.6,-2.2) AE41(11.3,-2.2) AF1(-10.95,-2.75) AF2(-10.25,-2.75) AF40(10.25,-2.75) AF41(10.95,-2.75) AG1(-11.3,-3.3) AG2(-10.6,-3.3) AG3(-9.9,-3.3) AG39(9.9,-3.3) AG40(10.6,-3.3) AG41(11.3,-3.3) AH1(-10.95,-3.85) AH2(-10.25,-3.85) AH40(10.25,-3.85) AH41(10.95,-3.85) AJ1(-11.3,-4.4) AJ2(-10.6,-4.4) AJ3(-9.9,-4.4) AJ39(9.9,-4.4) AJ40(10.6,-4.4) AJ41(11.3,-4.4) AK1(-10.95,-4.95) AK2(-10.25,-4.95) AK40(10.25,-4.95) AK41(10.95,-4.95) AL1(-11.3,-5.5) AL2(-10.6,-5.5) AL3(-9.9,-5.5) AL39(9.9,-5.5) AL40(10.6,-5.5) AL41(11.3,-5.5) AM1(-10.95,-6.05) AM2(-10.25,-6.05) AM40(10.25,-6.05) AM41(10.95,-6.05) AN1(-11.3,-6.6) AN2(-10.6,-6.6) AN3(-9.9,-6.6) AN39(9.9,-6.6) AN40(10.6,-6.6) AN41(11.3,-6.6) AP1(-10.95,-7.15) AP2(-10.25,-7.15) AP40(10.25,-7.15) AP41(10.95,-7.15) AR1(-11.3,-7.7) AR2(-10.6,-7.7) AR3(-9.9,-7.7) AR39(9.9,-7.7) AR40(10.6,-7.7) AR41(11.3,-7.7) AT1(-10.95,-8.25) AT2(-10.25,-8.25) AT40(10.25,-8.25) AT41(10.95,-8.25) AU1(-11.3,-8.8) AU2(-10.6,-8.8) AU3(-9.9,-8.8) AU39(9.9,-8.8) AU40(10.6,-8.8) AU41(11.3,-8.8) AV1(-10.95,-9.35) AV2(-10.25,-9.35) AV40(10.25,-9.35) AV41(10.95,-9.35) AW2(-10.6,-9.9) AW3(-9.9,-9.9) AW5(-8.8,-9.9) AW7(-7.7,-9.9) AW9(-6.6,-9.9) AW11(-5.5,-9.9) AW13(-4.4,-9.9) AW15(-3.3,-9.9) AW17(-2.2,-9.9) AW19(-1.1,-9.9) AW21(0,-9.9) AW23(1.1,-9.9) AW25(2.2,-9.9) AW27(3.3,-9.9) AW29(4.4,-9.9) AW31(5.5,-9.9) AW33(6.6,-9.9) AW35(7.7,-9.9) AW37(8.8,-9.9) AW39(9.9,-9.9) AW40(10.6,-9.9) AY3(-9.9,-10.6) AY4(-9.35,-10.25) AY5(-8.8,-10.6) AY6(-8.25,-10.25) AY7(-7.7,-10.6) AY8(-7.15,-10.25) AY9(-6.6,-10.6) AY10(-6.05,-10.25) AY11(-5.5,-10.6) AY12(-4.95,-10.25) AY13(-4.4,-10.6) AY14(-3.85,-10.25) AY15(-3.3,-10.6) AY16(-2.75,-10.25) AY17(-2.2,-10.6) AY18(-1.65,-10.25) AY19(-1.1,-10.6) AY20(-0.55,-10.25) AY21(0,-10.6) AY22(0.55,-10.25) AY23(1.1,-10.6) AY24(1.65,-10.25) AY25(2.2,-10.6) AY26(2.75,-10.25) AY27(3.3,-10.6) AY28(3.85,-10.25) AY29(4.4,-10.6) AY30(4.95,-10.25) AY31(5.5,-10.6) AY32(6.05,-10.25) AY33(6.6,-10.6) AY34(7.15,-10.25) AY35(7.7,-10.6) AY36(8.25,-10.25) AY37(8.8,-10.6) AY38(9.35,-10.25) AY39(9.9,-10.6) B3(-9.9,10.6) B4(-9.35,10.25) B5(-8.8,10.6) B6(-8.25,10.25) B7(-7.7,10.6) B8(-7.15,10.25) B9(-6.6,10.6) B10(-6.05,10.25) B11(-5.5,10.6) B12(-4.95,10.25) B13(-4.4,10.6) B14(-3.85,10.25) B15(-3.3,10.6) B16(-2.75,10.25) B17(-2.2,10.6) B18(-1.65,10.25) B19(-1.1,10.6) B20(-0.55,10.25) B21(0,10.6) B22(0.55,10.25) B23(1.1,10.6) B24(1.65,10.25) B25(2.2,10.6) B26(2.75,10.25) B27(3.3,10.6) B28(3.85,10.25) B29(4.4,10.6) B30(4.95,10.25) B31(5.5,10.6) B32(6.05,10.25) B33(6.6,10.6) B34(7.15,10.25) B35(7.7,10.6) B36(8.25,10.25) B37(8.8,10.6) B38(9.35,10.25) B39(9.9,10.6) BA4(-9.35,-10.95) BA5(-8.8,-11.3) BA6(-8.25,-10.95) BA7(-7.7,-11.3) BA8(-7.15,-10.95) BA9(-6.6,-11.3) BA10(-6.05,-10.95) BA11(-5.5,-11.3) BA12(-4.95,-10.95) BA13(-4.4,-11.3) BA14(-3.85,-10.95) BA15(-3.3,-11.3) BA16(-2.75,-10.95) BA17(-2.2,-11.3) BA18(-1.65,-10.95) BA19(-1.1,-11.3) BA20(-0.55,-10.95) BA21(0,-11.3) BA22(0.55,-10.95) BA23(1.1,-11.3) BA24(1.65,-10.95) BA25(2.2,-11.3) BA26(2.75,-10.95) BA27(3.3,-11.3) BA28(3.85,-10.95) BA29(4.4,-11.3) BA30(4.95,-10.95) BA31(5.5,-11.3) BA32(6.05,-10.95) BA33(6.6,-11.3) BA34(7.15,-10.95) BA35(7.7,-11.3) BA36(8.25,-10.95) BA37(8.8,-11.3) BA38(9.35,-10.95) C2(-10.6,9.9) C3(-9.9,9.9) C5(-8.8,9.9) C7(-7.7,9.9) C9(-6.6,9.9) C11(-5.5,9.9) C13(-4.4,9.9) C15(-3.3,9.9) C17(-2.2,9.9) C19(-1.1,9.9) C21(0,9.9) C23(1.1,9.9) C25(2.2,9.9) C27(3.3,9.9) C29(4.4,9.9) C31(5.5,9.9) C33(6.6,9.9) C35(7.7,9.9) C37(8.8,9.9) C39(9.9,9.9) C40(10.6,9.9) D1(-10.95,9.35) D2(-10.25,9.35) D40(10.25,9.35) D41(10.95,9.35) E1(-11.3,8.8) E2(-10.6,8.8) E3(-9.9,8.8) E39(9.9,8.8) E40(10.6,8.8) E41(11.3,8.8) F1(-10.95,8.25) F2(-10.25,8.25) F40(10.25,8.25) F41(10.95,8.25) G1(-11.3,7.7) G2(-10.6,7.7) G3(-9.9,7.7) G39(9.9,7.7) G40(10.6,7.7) G41(11.3,7.7) H1(-10.95,7.15) H2(-10.25,7.15) H40(10.25,7.15) H41(10.95,7.15) J1(-11.3,6.6) J2(-10.6,6.6) J3(-9.9,6.6) J39(9.9,6.6) J40(10.6,6.6) J41(11.3,6.6) K1(-10.95,6.05) K2(-10.25,6.05) K40(10.25,6.05) K41(10.95,6.05) L1(-11.3,5.5) L2(-10.6,5.5) L3(-9.9,5.5) L39(9.9,5.5) L40(10.6,5.5) L41(11.3,5.5) M1(-10.95,4.95) M2(-10.25,4.95) M40(10.25,4.95) M41(10.95,4.95) N1(-11.3,4.4) N2(-10.6,4.4) N3(-9.9,4.4) N39(9.9,4.4) N40(10.6,4.4) N41(11.3,4.4) P1(-10.95,3.85) P2(-10.25,3.85) P40(10.25,3.85) P41(10.95,3.85) R1(-11.3,3.3) R2(-10.6,3.3) R3(-9.9,3.3) R39(9.9,3.3) R40(10.6,3.3) R41(11.3,3.3) T1(-10.95,2.75) T2(-10.25,2.75) T40(10.25,2.75) T41(10.95,2.75) U1(-11.3,2.2) U2(-10.6,2.2) U3(-9.9,2.2) U39(9.9,2.2) U40(10.6,2.2) U41(11.3,2.2) V1(-10.95,1.65) V2(-10.25,1.65) V40(10.25,1.65) V41(10.95,1.65) W1(-11.3,1.1) W2(-10.6,1.1) W3(-9.9,1.1) W39(9.9,1.1) W40(10.6,1.1) W41(11.3,1.1) Y1(-10.95,0.55) Y2(-10.25,0.55) Y40(10.25,0.55) Y41(10.95,0.55)
C100LS-10809-L
  round 1.27 hole 0.914: 1(3.556,6.06) 2(2.54,4.96) 3(1.524,6.06) 4(0.508,4.96) 5(-0.508,6.06) 6(-1.524,4.96) 7(-2.54,6.06) 8(-3.556,4.96)
  oval 1.321x3.124 hole 0.61x2.413: 9(8.3,0) 10(-8.3,0)
C166KK-12209-L
  round 0.254 hole 1.27 unplated: (-15.595,0) (15.595,0)
  oval 1.727x3.124 hole 1.016x2.413: 23(18.075,1.11) 24(-18.075,1.11)
  oval 1.041x1.168 hole 0.762: P1(1.905,1.84) P2(0.635,1.84) P3(-0.635,1.84) P4(-1.905,1.84) P5(-3.175,1.84) P6(-4.445,1.84) P7(-5.715,1.84) P8(-6.985,1.84) P9(-8.255,1.84) P10(-9.525,1.84) P11(-10.795,1.84) P12(-12.065,1.84) P13(-13.335,1.84) P14(-14.605,1.84) P15(-15.875,1.84) S1(15.875,1.84) S2(14.605,1.84) S3(13.335,1.84) S4(12.065,1.84) S5(10.795,1.84) S6(9.525,1.84) S7(8.255,1.84)
C402-TO0D2H26
  custom 0.152x0.152 smd: 1(0,0.457) 2(0,-0.457)
C402H20
  custom 0.152x0.152 smd: 1(0,0.445) 2(0,-0.445)
C402H22
  custom 0.152x0.152 smd: 1(0,0.445) 2(0,-0.445)
C603
  custom 0.216x0.216 smd: 1(0,0.762) 2(0,-0.762)
C603H36
  custom 0.216x0.216 smd: 1(0,0.762) 2(0,-0.762)
C603H38
  custom 0.216x0.216 smd: 1(0,0.762) 2(0,-0.762)
C603H40
  custom 0.216x0.216 smd: 1(0,0.762) 2(0,-0.762)
C805H50
  rect 1.397x1.143 smd: 1(0,0.965) 2(0,-0.965)
C805H54
  rect 1.397x1.143 smd: 1(0,0.965) 2(0,-0.965)
C805H56
  rect 1.397x1.143 smd: 1(0,0.965) 2(0,-0.965)
C805H58
  rect 1.397x1.143 smd: 1(0,0.965) 2(0,-0.965)
C1206H71
  rect 1.651x1.27 smd: 1(0,1.397) 2(0,-1.397)
CI0102M1HR0-LF
  rect 0.991x3.505 smd: 1(1,-5.75) 2(-1,-5.75)
  rect 1.499x3.404 smd: 3(3.35,0) 4(-3.35,0)
CON2C-U
  custom 0.171x0.171 smd: 1(0,0.533) 2(0,-0.533)
CON2O-U
  custom 0.159x0.159 smd: 1(0,0.254) 2(0,-0.254)
CT7343H83
  rect 2.413x2.286 smd: 1(0,3.15) 2(0,-3.15)
D4724AKH44
  rect 2.007x1.549 smd: A(0,2.221) K(0,-2.221)
D5436AKH97
  rect 2.286x2.032 smd: A(0,2.438) K(0,-2.438)
DFN10G3-G265175H32
  rect 0.305x0.914 smd: 1(1,1.549) 2(0.5,1.549) 3(0,1.549) 4(-0.5,1.549) 5(-1,1.549) 6(-1,-1.549) 7(-0.5,-1.549) 8(0,-1.549) 9(0.5,-1.549) 10(1,-1.549)
  rect 2.642x1.753 smd: 11(0,0)
DFN10G2510H26
  rect 0.305x0.787 smd: 1(1,0.494) 5(-1,0.494) 6(-1,-0.494) 10(1,-0.494)
  rect 0.254x0.787 smd: 2(0.521,0.494) 4(-0.521,0.494) 7(-0.521,-0.494) 9(0.521,-0.494)
  rect 0.025x0.025 smd: 3(0,0.494)
  rect 0.406x1.753 smd: 8(0,-0.494)
DM-ASP-137098-05-01
  rect 0.737x2.794 smd: 1(-5.715,-2.035) 2(-5.715,2.035) 3(-4.445,-2.035) 4(-4.445,2.035) 5(-3.175,-2.035) 6(-3.175,2.035) 7(-1.905,-2.035) 8(-1.905,2.035) 9(-0.635,-2.035) 10(-0.635,2.035) 11(0.635,-2.035) 12(0.635,2.035) 13(1.905,-2.035) 14(1.905,2.035) 15(3.175,-2.035) 16(3.175,2.035) 17(4.445,-2.035) 18(4.445,2.035) 19(5.715,-2.035) 20(5.715,2.035)
G6179-1000000-U
  rect 0.635x2.108 smd: 1(1.905,3.47) 2(0.635,3.47) 3(-0.635,3.47) 4(-1.905,3.47) 5(-1.905,-3.47) 6(-0.635,-3.47) 7(0.635,-3.47) 8(1.905,-3.47)
GAP-CLOSE-PWR-3
  rect 0.66x0.762 smd: 1(-0.305,0) 2(0.305,0)
GENS315R158-8-F-A
  round 0.254 hole 4.013 unplated: (0,0)
  round 0.864 hole 0.508: 1(-0.634,3.189) 2(-2.703,1.806) 3(-3.189,-0.634) 4(-1.806,-2.703) 5(0.634,-3.189) 6(2.703,-1.806) 7(3.189,0.634) 8(1.806,2.703)
HTJ-035-24FBSPT
  round 0.254 hole 1.118 unplated: (0,0) (0,-5)
  round 1.524 hole 1.118: 1(-4.45,0) 2(-3.6,-5) 3(1.6,-8.1) 7(4.8,0) 8(3.1,-6.1) 9(4.5,-8.1)
L603H38
  custom 0.216x0.216 smd: 1(0,0.762) 2(0,-0.762)
L805H42
  rect 1.397x1.143 smd: 1(0,0.965) 2(0,-0.965)
L1608-UH38
  custom 0.216x0.216 smd: 1(0,0.762) 2(0,-0.762)
L3030-3009H40
  rect 3.251x1.524 smd: 1(0,1.108) 2(0,-1.108)
L3330-1230H95
  rect 3.251x1.778 smd: 1(0,1.135) 2(0,-1.135)
L115100-2H158
  rect 3.759x3.251 smd: 1(0,5.022) 2(0,-5.022)
L120120-5022-2H237
  rect 11.989x5.69 smd: 1(0,5.09) 2(0,-5.09)
L125100-4P-1H24
  rect 0.762x0.432 smd: 1(0.625,0.341) 2(-0.625,0.341) 3(-0.625,-0.341) 4(0.625,-0.341)
L125100-4P-1H28
  rect 0.762x0.432 smd: 1(0.625,0.341) 2(-0.625,0.341) 3(-0.625,-0.341) 4(0.625,-0.341)
L125100-4P-1H37
  rect 0.762x0.432 smd: 1(0.625,0.341) 2(-0.625,0.341) 3(-0.625,-0.341) 4(0.625,-0.341)
L125100-4P-4H24
  rect 0.762x0.432 smd: 1(-0.625,0.341) 2(0.625,0.341) 3(0.625,-0.341) 4(-0.625,-0.341)
L686647-127318H119
  rect 3.683x2.413 smd: 1(0,2.986) 2(0,-2.986)
LQFP64H63
  rect 0.203x1.524 smd: 1(3,4.242) 2(2.6,4.242) 3(2.2,4.242) 4(1.8,4.242) 5(1.4,4.242) 6(0.999,4.242) 7(0.599,4.242) 8(0.199,4.242) 9(-0.199,4.242) 10(-0.599,4.242) 11(-0.999,4.242) 12(-1.4,4.242) 13(-1.8,4.242) 14(-2.2,4.242) 15(-2.6,4.242) 16(-3,4.242) 33(-3,-4.242) 34(-2.6,-4.242) 35(-2.2,-4.242) 36(-1.8,-4.242) 37(-1.4,-4.242) 38(-0.999,-4.242) 39(-0.599,-4.242) 40(-0.199,-4.242) 41(0.199,-4.242) 42(0.599,-4.242) 43(0.999,-4.242) 44(1.4,-4.242) 45(1.8,-4.242) 46(2.2,-4.242) 47(2.6,-4.242) 48(3,-4.242)
  rect 1.524x0.203 smd: 17(-4.242,3) 18(-4.242,2.6) 19(-4.242,2.2) 20(-4.242,1.8) 21(-4.242,1.4) 22(-4.242,0.999) 23(-4.242,0.599) 24(-4.242,0.199) 25(-4.242,-0.199) 26(-4.242,-0.599) 27(-4.242,-0.999) 28(-4.242,-1.4) 29(-4.242,-1.8) 30(-4.242,-2.2) 31(-4.242,-2.6) 32(-4.242,-3) 49(4.242,-3) 50(4.242,-2.6) 51(4.242,-2.2) 52(4.242,-1.8) 53(4.242,-1.4) 54(4.242,-0.999) 55(4.242,-0.599) 56(4.242,-0.199) 57(4.242,0.199) 58(4.242,0.599) 59(4.242,0.999) 60(4.242,1.4) 61(4.242,1.8) 62(4.242,2.2) 63(4.242,2.6) 64(4.242,3)
NTC-402H22-U
  custom 0.14x0.14 smd: 1(0,0.445) 2(0,-0.445)
NTC-402H24-U
  custom 0.14x0.14 smd: 1(0,0.445) 2(0,-0.445)
OSC-3225-4P-3H36
  rect 1.397x0.914 smd: 1(-1.171,-0.825) 2(1.171,-0.825) 3(1.171,0.825) 4(-1.171,0.825)
OSC-3225-4P-4H36
  rect 1.397x1.067 smd: 1(-1.171,-0.756) 2(1.171,-0.756) 3(1.171,0.756) 4(-1.171,0.756)
POLYSW-2114H30
  rect 1.6x0.965 smd: 1(0,0.94) 2(0,-0.94)
POLYSW-3217-UH63
  rect 1.905x1.143 smd: 1(0,1.418) 2(0,-1.418)
POLYSW-4633-1H63
  rect 3.505x1.245 smd: 1(0,2.059) 2(0,-2.059)
PPAK-8P-3232H36
  rect 0.406x0.914 smd: 1(-0.975,-2.396) 2(-0.325,-2.396) 3(0.325,-2.396) 4(0.975,-2.396)
  rect 3.353x2.692 smd: 5(0,0)
  rect 0.025x0.025 smd: 6(0.65,0.838) 7(0,0.838) 8(-0.65,0.838)
PPAK-8P-5262H40
  rect 0.762x1.448 smd: 1(-1.905,-3.684) 2(-0.635,-3.684) 3(0.635,-3.684) 4(1.905,-3.684)
  rect 5.512x5.309 smd: 5(0,0)
  rect 0.025x0.025 smd: 6(0.635,2.146) 7(-0.635,2.146) 8(-1.905,2.146)
PQFP128H134
  rect 0.305x1.778 smd: 1(9.249,8.217) 2(8.75,8.217) 3(8.25,8.217) 4(7.75,8.217) 5(7.25,8.217) 6(6.75,8.217) 7(6.25,8.217) 8(5.751,8.217) 9(5.25,8.217) 10(4.75,8.217) 11(4.249,8.217) 12(3.75,8.217) 13(3.25,8.217) 14(2.75,8.217) 15(2.25,8.217) 16(1.75,8.217) 17(1.25,8.217) 18(0.751,8.217) 19(0.25,8.217) 20(-0.25,8.217) 21(-0.751,8.217) 22(-1.25,8.217) 23(-1.75,8.217) 24(-2.25,8.217) 25(-2.75,8.217) 26(-3.25,8.217) 27(-3.75,8.217) 28(-4.249,8.217) 29(-4.75,8.217) 30(-5.25,8.217) 31(-5.751,8.217) 32(-6.25,8.217) 33(-6.75,8.217) 34(-7.25,8.217) 35(-7.75,8.217) 36(-8.25,8.217) 37(-8.75,8.217) 38(-9.249,8.217) 65(-9.249,-8.217) 66(-8.75,-8.217) 67(-8.25,-8.217) 68(-7.75,-8.217) 69(-7.25,-8.217) 70(-6.75,-8.217) 71(-6.25,-8.217) 72(-5.751,-8.217) 73(-5.25,-8.217) 74(-4.75,-8.217) 75(-4.249,-8.217) 76(-3.75,-8.217) 77(-3.25,-8.217) 78(-2.75,-8.217) 79(-2.25,-8.217) 80(-1.75,-8.217) 81(-1.25,-8.217) 82(-0.751,-8.217) 83(-0.25,-8.217) 84(0.25,-8.217) 85(0.751,-8.217) 86(1.25,-8.217) 87(1.75,-8.217) 88(2.25,-8.217) 89(2.75,-8.217) 90(3.25,-8.217) 91(3.75,-8.217) 92(4.249,-8.217) 93(4.75,-8.217) 94(5.25,-8.217) 95(5.751,-8.217) 96(6.25,-8.217) 97(6.75,-8.217) 98(7.25,-8.217) 99(7.75,-8.217) 100(8.25,-8.217) 101(8.75,-8.217) 102(9.249,-8.217)
  rect 1.778x0.305 smd: 39(-11.214,6.25) 40(-11.214,5.751) 41(-11.214,5.25) 42(-11.214,4.75) 43(-11.214,4.249) 44(-11.214,3.75) 45(-11.214,3.25) 46(-11.214,2.75) 47(-11.214,2.25) 48(-11.214,1.75) 49(-11.214,1.25) 50(-11.214,0.751) 51(-11.214,0.25) 52(-11.214,-0.25) 53(-11.214,-0.751) 54(-11.214,-1.25) 55(-11.214,-1.75) 56(-11.214,-2.25) 57(-11.214,-2.75) 58(-11.214,-3.25) 59(-11.214,-3.75) 60(-11.214,-4.249) 61(-11.214,-4.75) 62(-11.214,-5.25) 63(-11.214,-5.751) 64(-11.214,-6.25) 103(11.214,-6.25) 104(11.214,-5.751) 105(11.214,-5.25) 106(11.214,-4.75) 107(11.214,-4.249) 108(11.214,-3.75) 109(11.214,-3.25) 110(11.214,-2.75) 111(11.214,-2.25) 112(11.214,-1.75) 113(11.214,-1.25) 114(11.214,-0.751) 115(11.214,-0.25) 116(11.214,0.25) 117(11.214,0.751) 118(11.214,1.25) 119(11.214,1.75) 120(11.214,2.25) 121(11.214,2.75) 122(11.214,3.25) 123(11.214,3.75) 124(11.214,4.249) 125(11.214,4.75) 126(11.214,5.25) 127(11.214,5.751) 128(11.214,6.25)
PSDAT0-09GLBS1ZZ4H1-1
  round 0.254 hole 1.702 unplated: (-12.65,0) (12.65,0)
  rect 0.991x2.54 smd: 1(-7.57,8.12) 2(-5.07,8.12) 3(-2.57,8.12) 4(-0.07,8.12) 5(2.43,8.12) 6(4.93,8.12) 7(7.43,8.12) 8(9.055,8.12) 9(-10.07,8.12) 10(10.875,8.12) 11(-11.755,8.12)
  rect 2.057x2.489 smd: 12(-15.229,-8.35) 13(15.229,-8.35)
QFN20-G1D75H32
  rect 0.203x0.914 smd: 1(0.8,1.551) 2(0.4,1.551) 3(0,1.551) 4(-0.4,1.551) 5(-0.8,1.551) 11(-0.8,-1.551) 12(-0.4,-1.551) 13(0,-1.551) 14(0.4,-1.551) 15(0.8,-1.551)
  rect 0.914x0.203 smd: 6(-1.551,0.8) 7(-1.551,0.4) 8(-1.551,0) 9(-1.551,-0.4) 10(-1.551,-0.8) 16(1.551,-0.8) 17(1.551,-0.4) 18(1.551,0) 19(1.551,0.4) 20(1.551,0.8)
  rect 1.753x1.753 smd: 21(0,0)
QFN20-G2D1H34
  rect 0.305x1.092 smd: 1(0.999,1.956) 5(-0.999,1.956) 11(-0.999,-1.956) 15(0.999,-1.956)
  rect 0.305x1.143 smd: 2(0.5,1.93) 3(0,1.93) 4(-0.5,1.93) 12(-0.5,-1.93) 13(0,-1.93) 14(0.5,-1.93)
  rect 1.092x0.305 smd: 6(-1.956,0.999) 10(-1.956,-0.999) 16(1.956,-0.999) 20(1.956,0.999)
  rect 1.143x0.305 smd: 7(-1.93,0.5) 8(-1.93,0) 9(-1.93,-0.5) 17(1.93,-0.5) 18(1.93,0) 19(1.93,0.5)
  rect 2.108x2.108 smd: 21(0,0)
QFN32J4-G2D85H36
  rect 0.203x0.864 smd: 1(1.4,2.085) 2(1,2.085) 3(0.6,2.085) 4(0.2,2.085) 5(-0.2,2.085) 6(-0.6,2.085) 7(-1,2.085) 8(-1.4,2.085) 17(-1.4,-2.085) 18(-1,-2.085) 19(-0.6,-2.085) 20(-0.2,-2.085) 21(0.2,-2.085) 22(0.6,-2.085) 23(1,-2.085) 24(1.4,-2.085)
  rect 0.864x0.203 smd: 9(-2.085,1.4) 10(-2.085,1) 11(-2.085,0.6) 12(-2.085,0.2) 13(-2.085,-0.2) 14(-2.085,-0.6) 15(-2.085,-1) 16(-2.085,-1.4) 25(2.085,-1.4) 26(2.085,-1) 27(2.085,-0.6) 28(2.085,-0.2) 29(2.085,0.2) 30(2.085,0.6) 31(2.085,1) 32(2.085,1.4)
  rect 2.845x2.845 smd: 33(0,0)
QFN40-G3D5H32
  rect 0.203x0.914 smd: 1(1.8,2.553) 10(-1.8,2.553) 21(-1.8,-2.553) 30(1.8,-2.553)
  rect 0.203x0.965 smd: 2(1.4,2.527) 3(1,2.527) 4(0.6,2.527) 5(0.2,2.527) 6(-0.2,2.527) 7(-0.6,2.527) 8(-1,2.527) 9(-1.4,2.527) 22(-1.4,-2.527) 23(-1,-2.527) 24(-0.6,-2.527) 25(-0.2,-2.527) 26(0.2,-2.527) 27(0.6,-2.527) 28(1,-2.527) 29(1.4,-2.527)
  rect 0.914x0.203 smd: 11(-2.553,1.8) 20(-2.553,-1.8) 31(2.553,-1.8) 40(2.553,1.8)
  rect 0.965x0.203 smd: 12(-2.527,1.4) 13(-2.527,1) 14(-2.527,0.6) 15(-2.527,0.2) 16(-2.527,-0.2) 17(-2.527,-0.6) 18(-2.527,-1) 19(-2.527,-1.4) 32(2.527,-1.4) 33(2.527,-1) 34(2.527,-0.6) 35(2.527,-0.2) 36(2.527,0.2) 37(2.527,0.6) 38(2.527,1) 39(2.527,1.4)
  rect 3.505x3.505 smd: 41(0,0)
QFN48J6-G4D55H40
  rect 0.203x1.016 smd: 1(2.2,3) 2(1.8,3) 3(1.4,3) 4(1,3) 5(0.6,3) 6(0.2,3) 7(-0.2,3) 8(-0.6,3) 9(-1,3) 10(-1.4,3) 11(-1.8,3) 12(-2.2,3) 25(-2.2,-3) 26(-1.8,-3) 27(-1.4,-3) 28(-1,-3) 29(-0.6,-3) 30(-0.2,-3) 31(0.2,-3) 32(0.6,-3) 33(1,-3) 34(1.4,-3) 35(1.8,-3) 36(2.2,-3)
  rect 1.016x0.203 smd: 13(-3,2.2) 14(-3,1.8) 15(-3,1.4) 16(-3,1) 17(-3,0.6) 18(-3,0.2) 19(-3,-0.2) 20(-3,-0.6) 21(-3,-1) 22(-3,-1.4) 23(-3,-1.8) 24(-3,-2.2) 37(3,-2.2) 38(3,-1.8) 39(3,-1.4) 40(3,-1) 41(3,-0.6) 42(3,-0.2) 43(3,0.2) 44(3,0.6) 45(3,1) 46(3,1.4) 47(3,1.8) 48(3,2.2)
  rect 4.547x4.547 smd: 49(0,0)
QFN48J6-G465H40
  rect 0.203x0.965 smd: 1(2.2,3.025) 2(1.8,3.025) 3(1.4,3.025) 4(1,3.025) 5(0.6,3.025) 6(0.2,3.025) 7(-0.2,3.025) 8(-0.6,3.025) 9(-1,3.025) 10(-1.4,3.025) 11(-1.8,3.025) 12(-2.2,3.025) 25(-2.2,-3.025) 26(-1.8,-3.025) 27(-1.4,-3.025) 28(-1,-3.025) 29(-0.6,-3.025) 30(-0.2,-3.025) 31(0.2,-3.025) 32(0.6,-3.025) 33(1,-3.025) 34(1.4,-3.025) 35(1.8,-3.025) 36(2.2,-3.025)
  rect 0.965x0.203 smd: 13(-3.025,2.2) 14(-3.025,1.8) 15(-3.025,1.4) 16(-3.025,1) 17(-3.025,0.6) 18(-3.025,0.2) 19(-3.025,-0.2) 20(-3.025,-0.6) 21(-3.025,-1) 22(-3.025,-1.4) 23(-3.025,-1.8) 24(-3.025,-2.2) 37(3.025,-2.2) 38(3.025,-1.8) 39(3.025,-1.4) 40(3.025,-1) 41(3.025,-0.6) 42(3.025,-0.2) 43(3.025,0.2) 44(3.025,0.6) 45(3.025,1) 46(3.025,1.4) 47(3.025,1.8) 48(3.025,2.2)
  rect 4.648x4.648 smd: 49(0,0)
R402H14
  custom 0.14x0.14 smd: 1(0,0.445) 2(0,-0.445)
R402H16
  custom 0.14x0.14 smd: 1(0,0.445) 2(0,-0.445)
R603H22
  custom 0.216x0.216 smd: 1(0,0.762) 2(0,-0.762)
R805H24
  rect 1.397x1.143 smd: 1(0,0.965) 2(0,-0.965)
R1206H26
  rect 1.651x1.27 smd: 1(0,1.397) 2(0,-1.397)
R2512H32
  rect 3.505x1.778 smd: 1(0,2.794) 2(0,-2.794)
SE331721H237
  rect 1.422x3.556 smd: 1(0,2.574) 2(0,-2.574)
SE361416H237
  rect 1.422x3.556 smd: 1(0,2.574) 2(0,-2.574)
SKRBAAE010
  rect 1.473x0.813 smd: 1(-1.971,1.825) 2(-1.971,-1.825) 3(1.971,1.825) 4(1.971,-1.825)
SKT-HDMI23-150122-9
  rect 0.305x2.591 smd: 1(4.5,0.76) 2(4,0.76) 3(3.5,0.76) 4(3,0.76) 5(2.5,0.76) 6(2,0.76) 7(1.5,0.76) 8(1,0.76) 9(0.5,0.76) 10(0,0.76) 11(-0.5,0.76) 12(-1,0.76) 13(-1.5,0.76) 14(-2,0.76) 15(-2.5,0.76) 16(-3,0.76) 17(-3.5,0.76) 18(-4,0.76) 19(-4.5,0.76)
  oval 1.626x3.429 hole 0.914x2.718: 20(7.25,0) 21(-7.25,0)
  oval 1.626x2.819 hole 0.914x2.108: 22(7.25,-5.96) 23(-7.25,-5.96)
SKT-USB6-145137-6
  round 1.346 hole 0.94: 1(3.5,2.71) 2(1,2.71) 3(-1,2.71) 4(-3.5,2.71)
  oval 1.524x3.2 hole 0.813x2.489: 5(-6.5,0) 6(6.5,0)
SKT-USB11-139165-9
  round 1.067 hole 0.711: 1(3.5,3.5) 2(1,3.5) 3(-1,3.5) 4(-3.5,3.5) 5(-4,2) 6(-2,2) 7(0,2) 8(2,2) 9(4,2)
  oval 1.422x3.302 hole 0.711x2.591: 10(-6.4,0) 11(6.4,0)
SLP2510P8-1H22
  rect 0.305x0.762 smd: 1(-1,-0.5) 5(1,-0.5) 6(1,0.5) 10(-1,0.5)
  rect 0.203x0.762 smd: 2(-0.5,-0.5) 4(0.5,-0.5) 7(0.5,0.5) 9(-0.5,0.5)
  rect 0.406x0.762 smd: 3(0,-0.5) 8(0,0.5)
SMD49-6914-0403H56
  rect 1.168x0.559 smd: 1(-3.38,-0.427) 2(3.38,-0.427) 3(3.38,0.427) 4(-3.38,0.427)
SMD-ARES4-2H18-U
  rect 0.305x0.406 smd: 1(-0.25,-0.305) 2(0.25,-0.305) 3(0.25,0.305) 4(-0.25,0.305)
SMD-ARES4H18
  rect 0.356x0.66 smd: 1(-0.325,-0.599) 2(0.325,-0.599) 3(0.325,0.599) 4(-0.325,0.599)
SOD323AKH40
  rect 0.559x1.016 smd: A(0,1.143) K(0,-1.143)
SOD-523-4H28
  rect 0.559x0.864 smd: 1(0,0.778) 2(0,-0.778)
SOIC8-1H86
  rect 0.635x1.651 smd: 1(-1.905,-3.493) 2(-0.635,-3.493) 3(0.635,-3.493) 4(1.905,-3.493) 5(1.905,3.493) 6(0.635,3.493) 7(-0.635,3.493) 8(-1.905,3.493)
SOIC8H69
  rect 0.635x1.651 smd: 1(-1.905,-2.54) 2(-0.635,-2.54) 3(0.635,-2.54) 4(1.905,-2.54) 5(1.905,2.54) 6(0.635,2.54) 7(-0.635,2.54) 8(-1.905,2.54)
SOIC8H75
  rect 0.635x1.651 smd: 1(-1.905,-2.54) 2(-0.635,-2.54) 3(0.635,-2.54) 4(1.905,-2.54) 5(1.905,2.54) 6(0.635,2.54) 7(-0.635,2.54) 8(-1.905,2.54)
SON14J3020-G2610H32
  rect 0.025x0.025 smd: 1(1.2,1.105) 6(-0.8,1.105) 9(-0.8,-1.105) 14(1.2,-1.105)
  custom 0.151x0.151 smd: 2(0.8,1.105) 7(-1.2,1.105) 8(-1.2,-1.105) 13(0.8,-1.105)
  rect 0.203x0.813 smd: 3(0.4,1.105) 4(0,1.105) 5(-0.4,1.105) 10(-0.4,-1.105) 11(0,-1.105) 12(0.4,-1.105)
  rect 2.591x0.889 smd: 15(0,0)
